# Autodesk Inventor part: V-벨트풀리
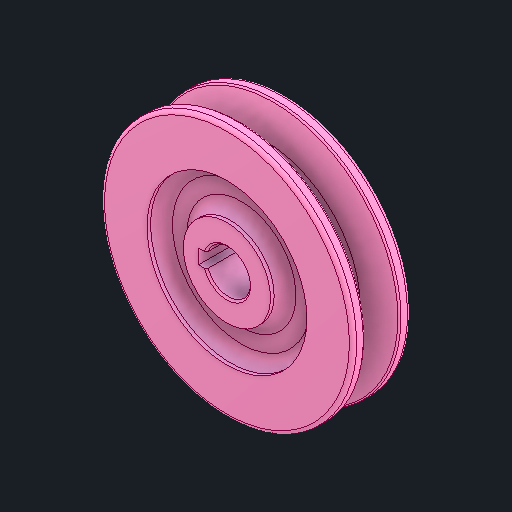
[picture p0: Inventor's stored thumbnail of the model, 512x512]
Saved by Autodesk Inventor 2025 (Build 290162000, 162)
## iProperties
Created: 2025-08
Part Number: V-벨트풀리
Material: 강철, 연강
Document SubType Name: Modeling
Designer: infra023
Density: 7.86 g/cm^3
Appearance: 기본값
Author: jhkim
Sending System: Autodesk Inventor 2026
Preprocessor: ST-DEVELOPER v20.1
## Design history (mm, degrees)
feature "Solid1"
node "솔리드1"
